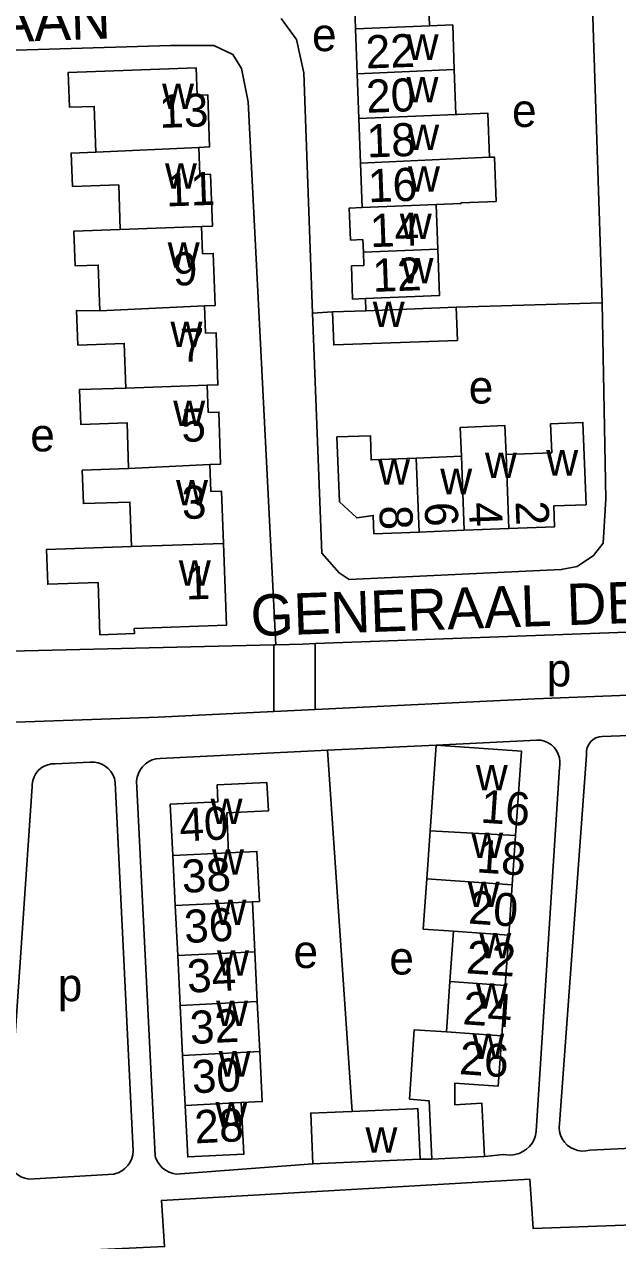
# Model space of a CAD drawing. Extents: x 159294 to 161936, y 384538 to 386517.
# Drawn here: x 161739.3 to 161811.1, y 386264.2 to 386411.4 of the extents above; entities that cross this region are included whole.
import ezdxf

# ---------------------------------------------------------------- set-up
doc = ezdxf.new("R2010")
doc.units = 0
for name, color, linetype in [('BLT_Basislijn', 7, 'Continuous'), ('BLT_Bebouwing', 7, 'Continuous'), ('BLT_Centroide', 7, 'Continuous'), ('BLT_Huisnummer', 7, 'Continuous'), ('BLT_Huisnummer_ tussenligend', 7, 'Continuous'), ('BLT_Onderverdeling_panden', 7, 'Continuous'), ('BLT_Straatnaam', 7, 'Continuous')]:
    doc.layers.add(name, color=color, linetype=linetype)

msp = doc.modelspace()

# ---------------------------------------------------------------- linework, layer by layer
at = {"layer": 'BLT_Basislijn'}
for p, q in [((161807.9, 386417.77), (161809.21, 386377.72)), ((161780.62, 386376.75), (161780.56, 386378.21)), ((161791.55, 386377.17), (161809.21, 386377.72)), ((161776.58, 386376.6), (161774.14, 386376.44)), ((161774.49, 386336.47), (161849.43, 386339.2)), ((161769.49, 386336.33), (161712.37, 386334.96)), ((161769.7, 386336.34), (161769.49, 386336.33)), ((161769.49, 386336.33), (161769.49, 386328.26)), ((161772.98, 386336.42), (161769.7, 386336.34)), ((161772.98, 386336.42), (161774.49, 386336.47)), ((161774.49, 386336.47), (161774.49, 386328.5)), ((161801.09, 386329.8), (161849.76, 386331.65)), ((161774.49, 386328.5), (161801.09, 386329.8)), ((161755.46, 386327.58), (161724.21, 386326.46)), ((161755.46, 386327.58), (161769.49, 386328.26)), ((161769.49, 386328.26), (161774.49, 386328.5)), ((161789.11, 386324.17), (161801.33, 386324.8)), ((161809.24, 386325.24), (161813.59, 386325.39)), ((161755.71, 386322.58), (161775.99, 386323.57)), ((161775.99, 386323.57), (161789.11, 386324.17)), ((161775.99, 386323.57), (161778.95, 386279.87)), ((161743.02, 386321.92), (161747.26, 386322.14)), ((161807.32, 386322.97), (161804.04, 386278.35)), ((161804.04, 386321.48), (161801.25, 386277.46)), ((161737.24, 386275.47), (161740.23, 386319.19)), ((161750.28, 386319.68), (161752.44, 386275.11)), ((161752.87, 386319.88), (161755.1, 386274.48)), ((161797.27, 386274.67), (161794.99, 386274.43)), ((161815.98, 386275.57), (161807.72, 386275.17)), ((161774.21, 386273.52), (161757.65, 386272.28)), ((161788.61, 386274.09), (161787.18, 386274.07)), ((161750.09, 386272.28), (161739.81, 386271.69))]:
    msp.add_line(p, q, dxfattribs=at)
for points in [[(161770.35, 386412.1), (161772.24, 386409.55), (161773.11, 386405.52), (161774.14, 386376.44)], [(161710.21, 386407.44), (161756.95, 386408.83), (161762.21, 386408.83), (161764.53, 386407.73), (161765.55, 386406.04), (161766.37, 386402.02), (161769.7, 386336.34)], [(161774.14, 386376.44), (161775.3, 386347.43), (161777.37, 386345.04), (161778.61, 386344.23), (161804.27, 386345.42), (161806.18, 386345.79), (161808.16, 386347.12), (161809.34, 386348.62), (161809.68, 386353.98), (161809.21, 386377.72)], [(161801.33, 386324.8), (161801.8, 386324.77), (161802.25, 386324.66), (161802.68, 386324.47), (161803.07, 386324.22), (161803.41, 386323.9), (161803.69, 386323.52), (161803.9, 386323.11), (161804.04, 386322.66), (161804.1, 386322.2), (161804.08, 386321.73), (161804.04, 386321.48)], [(161809.24, 386325.24), (161808.85, 386325.18), (161808.47, 386325.05), (161808.12, 386324.85), (161807.83, 386324.58), (161807.59, 386324.26), (161807.42, 386323.9), (161807.32, 386323.51), (161807.31, 386323.11), (161807.32, 386322.97)], [(161743.02, 386321.92), (161742.56, 386321.91), (161742.11, 386321.82), (161741.68, 386321.65), (161741.29, 386321.41), (161740.95, 386321.1), (161740.67, 386320.74), (161740.45, 386320.34), (161740.3, 386319.91), (161740.23, 386319.45), (161740.23, 386319.19)], [(161747.26, 386322.14), (161747.74, 386322.13), (161748.21, 386322.04), (161748.66, 386321.88), (161749.07, 386321.64), (161749.44, 386321.34), (161749.76, 386320.98), (161750.01, 386320.57), (161750.18, 386320.13), (161750.28, 386319.68)], [(161755.71, 386322.58), (161755.23, 386322.53), (161754.76, 386322.4), (161754.33, 386322.19), (161753.93, 386321.92), (161753.58, 386321.58), (161753.3, 386321.19), (161753.08, 386320.76), (161752.93, 386320.3), (161752.87, 386319.88)], [(161801.25, 386277.46), (161801.15, 386276.96), (161800.98, 386276.48), (161800.73, 386276.04), (161800.42, 386275.63), (161800.05, 386275.29), (161799.62, 386275), (161799.16, 386274.79), (161798.67, 386274.65), (161798.17, 386274.58), (161797.66, 386274.6), (161797.27, 386274.67)], [(161807.72, 386275.17), (161807.24, 386275.08), (161806.76, 386275.07), (161806.28, 386275.14), (161805.82, 386275.28), (161805.39, 386275.5), (161805, 386275.79), (161804.67, 386276.14), (161804.4, 386276.54), (161804.19, 386276.98), (161804.06, 386277.44), (161804.01, 386277.92), (161804.04, 386278.35)], [(161739.81, 386271.69), (161739.33, 386271.79), (161738.87, 386271.97), (161738.44, 386272.23), (161738.06, 386272.54), (161737.74, 386272.92), (161737.48, 386273.34), (161737.29, 386273.79), (161737.18, 386274.27), (161737.15, 386274.77), (161737.2, 386275.26), (161737.24, 386275.47)], [(161752.44, 386275.11), (161752.39, 386274.63), (161752.27, 386274.16), (161752.07, 386273.72), (161751.79, 386273.32), (161751.46, 386272.97), (161751.08, 386272.68), (161750.65, 386272.45), (161750.18, 386272.3), (161750.09, 386272.28)], [(161755.1, 386274.48), (161755.15, 386274.29), (161755.36, 386273.84), (161755.64, 386273.43), (161755.98, 386273.06), (161756.37, 386272.76), (161756.81, 386272.52), (161757.28, 386272.35), (161757.65, 386272.28)], [(161846.76, 386273.88), (161822.75, 386272.48), (161822.95, 386266.5), (161800.85, 386265.71), (161800.45, 386271.68), (161755.86, 386269.09), (161756.26, 386263.52), (161734.76, 386262.52), (161733.96, 386268.1)]]:
    msp.add_lwpolyline(points, dxfattribs=at)
at = {"layer": 'BLT_Bebouwing'}
for p, q in [((161779.18, 386416.22), (161779.37, 386410.84)), ((161788.34, 386411.21), (161788.14, 386416.61)), ((161779.37, 386410.84), (161779.57, 386405.41)), ((161779.57, 386405.41), (161779.77, 386399.99)), ((161779.77, 386399.99), (161779.96, 386394.6)), ((161779.96, 386394.6), (161780.16, 386389.24)), ((161789.32, 386384.2), (161789.12, 386389.6)), ((161780.62, 386376.75), (161776.58, 386376.6)), ((161791.55, 386377.17), (161780.62, 386376.75)), ((161791.7, 386373.15), (161791.55, 386377.17)), ((161792.18, 386359.13), (161786.71, 386358.92)), ((161787.07, 386349.97), (161792.53, 386350.18)), ((161792.53, 386350.18), (161797.93, 386350.4)), ((161798.74, 386313.26), (161799.45, 386323.46)), ((161788, 386308.01), (161788.4, 386313.8)), ((161798.33, 386307.29), (161798.74, 386313.26)), ((161757.25, 386310.82), (161757.55, 386304.78)), ((161797.91, 386301.2), (161798.33, 386307.29)), ((161757.55, 386304.78), (161757.85, 386298.73)), ((161767.18, 386299.19), (161766.89, 386305.24)), ((161790.79, 386295.58), (161791.21, 386301.66)), ((161797.49, 386295.11), (161797.91, 386301.2)), ((161757.85, 386298.73), (161758.15, 386292.68)), ((161767.48, 386293.15), (161767.18, 386299.19)), ((161790.37, 386289.49), (161790.79, 386295.58)), ((161797.07, 386289.02), (161797.49, 386295.11)), ((161758.15, 386292.68), (161758.44, 386286.64)), ((161767.78, 386287.1), (161767.48, 386293.15)), ((161796.65, 386282.93), (161797.07, 386289.02)), ((161758.44, 386286.64), (161758.74, 386280.59)), ((161777.87, 386279.83), (161778.95, 386279.87)), ((161778.95, 386279.87), (161786.38, 386280.19)), ((161787.18, 386274.07), (161774.21, 386273.52)), ((161788.61, 386274.09), (161794.99, 386274.43))]:
    msp.add_line(p, q, dxfattribs=at)
for points in [[(161791.32, 386405.93), (161791.13, 386411.32), (161788.34, 386411.21)], [(161760.4, 386396.51), (161761.7, 386396.56), (161761.48, 386402.87), (161760.18, 386402.82), (161760.06, 386406.12), (161744.6, 386405.58), (161744.75, 386401.37), (161747.74, 386401.47), (161747.94, 386395.93)], [(161791.52, 386400.5), (161791.32, 386405.93)], [(161795.6, 386395.31), (161795.38, 386400.67), (161791.73, 386400.51), (161791.52, 386400.5)], [(161747.94, 386395.93), (161744.94, 386395.82), (161745.09, 386391.78), (161750.7, 386391.97), (161750.89, 386386.57)], [(161760.74, 386386.92), (161762.04, 386386.97), (161761.82, 386393.27), (161760.52, 386393.23), (161760.4, 386396.51)], [(161789.12, 386389.6), (161792.15, 386389.73), (161792.14, 386389.82), (161796.38, 386389.97), (161796.18, 386395.33), (161795.6, 386395.31)], [(161780.16, 386389.24), (161778.6, 386389.17), (161778.76, 386385.29), (161780.25, 386385.35), (161780.35, 386383.85)], [(161750.89, 386386.57), (161745.27, 386386.38), (161745.42, 386382.18), (161748.23, 386382.28), (161748.42, 386376.74)], [(161761.07, 386377.33), (161762.37, 386377.37), (161762.15, 386383.69), (161760.86, 386383.64), (161760.74, 386386.92)], [(161780.35, 386383.85), (161780.37, 386382.21), (161778.86, 386382.16), (161779.01, 386378.15)], [(161780.56, 386378.21), (161789.52, 386378.58), (161789.32, 386384.2)], [(161779.01, 386378.15), (161780.56, 386378.21)], [(161748.42, 386376.74), (161745.61, 386376.79), (161745.76, 386372.59), (161751.38, 386372.79), (161751.56, 386367.39)], [(161761.42, 386367.74), (161762.71, 386367.78), (161762.49, 386374.09), (161761.19, 386374.04), (161761.07, 386377.33)], [(161776.58, 386376.6), (161776.73, 386372.62), (161791.7, 386373.15)], [(161751.56, 386367.39), (161745.95, 386367.2), (161746.1, 386363), (161751.71, 386363.19), (161751.9, 386357.65)], [(161761.75, 386358.14), (161763.04, 386358.19), (161762.82, 386364.49), (161761.53, 386364.44), (161761.42, 386367.74)], [(161797.6, 386359.34), (161797.46, 386362.86), (161792.05, 386362.63), (161792.18, 386359.13)], [(161797.93, 386350.4), (161803.47, 386350.61), (161803.37, 386353.13), (161807.28, 386353.28), (161806.89, 386363.23), (161802.98, 386363.07), (161803.12, 386359.56), (161797.6, 386359.34)], [(161786.71, 386358.92), (161781.25, 386358.7), (161781.17, 386361.63), (161777.12, 386361.47), (161777.42, 386353.61), (161779.51, 386351.68), (161781.51, 386351.98), (161781.6, 386349.76), (161787.07, 386349.97)], [(161751.9, 386357.65), (161746.29, 386357.45), (161746.43, 386353.41), (161752.05, 386353.6), (161752.24, 386348.21)], [(161763.38, 386348.6), (161763.15, 386354.9), (161761.86, 386354.86), (161761.75, 386358.14)], [(161752.24, 386348.21), (161741.95, 386347.85), (161742.1, 386343.65), (161748.21, 386343.86), (161748.43, 386337.55), (161752.6, 386337.69), (161752.58, 386338.31), (161763.73, 386338.7), (161763.38, 386348.6)], [(161789.11, 386324.17), (161788.4, 386313.8)], [(161799.45, 386323.46), (161789.11, 386324.17)], [(161764, 386311.16), (161763.77, 386315.99), (161768.83, 386316.23), (161768.65, 386319.65), (161762.6, 386319.37), (161762.71, 386317.33), (161756.94, 386317.05), (161757.25, 386310.82)], [(161766.89, 386305.24), (161767.74, 386305.28), (161767.43, 386311.33), (161764, 386311.16)], [(161791.21, 386301.66), (161787.57, 386301.92), (161788, 386308.01)], [(161790.37, 386289.49), (161786.47, 386289.74), (161785.92, 386281.34), (161788.27, 386281.16), (161788.61, 386274.09)], [(161765.54, 386280.93), (161768.08, 386281.05), (161767.78, 386287.1)], [(161791.38, 386280.67), (161791.4, 386283.3), (161796.65, 386282.93)], [(161758.74, 386280.59), (161759.05, 386274.37), (161765.85, 386274.7), (161765.54, 386280.93)], [(161794.99, 386274.43), (161794.66, 386280.85), (161791.38, 386280.67)], [(161774.21, 386273.52), (161773.95, 386279.66), (161777.87, 386279.83)], [(161786.38, 386280.19), (161786.92, 386280.21), (161787.18, 386274.07)]]:
    msp.add_lwpolyline(points, dxfattribs=at)
at = {"layer": 'BLT_Onderverdeling_panden'}
for p, q in [((161779.37, 386410.84), (161788.34, 386411.21)), ((161779.57, 386405.41), (161791.32, 386405.93)), ((161779.77, 386399.99), (161791.52, 386400.5)), ((161747.94, 386395.93), (161760.4, 386396.51)), ((161779.96, 386394.6), (161795.6, 386395.31)), ((161780.16, 386389.24), (161789.12, 386389.6)), ((161750.89, 386386.57), (161760.74, 386386.92)), ((161780.35, 386383.85), (161789.32, 386384.2)), ((161748.42, 386376.74), (161761.07, 386377.33)), ((161751.56, 386367.39), (161761.42, 386367.74)), ((161787.07, 386349.97), (161786.71, 386358.92)), ((161792.53, 386350.18), (161792.18, 386359.13)), ((161797.93, 386350.4), (161797.6, 386359.34)), ((161751.9, 386357.65), (161761.75, 386358.14)), ((161752.24, 386348.21), (161763.38, 386348.6)), ((161798.74, 386313.26), (161788.4, 386313.8)), ((161757.25, 386310.82), (161764, 386311.16)), ((161798.33, 386307.29), (161788, 386308.01)), ((161757.55, 386304.78), (161766.89, 386305.24)), ((161797.91, 386301.2), (161791.21, 386301.66)), ((161767.18, 386299.19), (161757.85, 386298.73)), ((161797.49, 386295.11), (161790.79, 386295.58)), ((161758.15, 386292.68), (161767.48, 386293.15)), ((161797.07, 386289.02), (161790.37, 386289.49)), ((161767.78, 386287.1), (161758.44, 386286.64)), ((161758.74, 386280.59), (161765.54, 386280.93))]:
    msp.add_line(p, q, dxfattribs=at)

# ---------------------------------------------------------------- texts
at = {"layer": 'BLT_Centroide'}
for s, p in [('e', (161774.1, 386408.16)), ('w', (161785.55, 386407.1)), ('w', (161755.95, 386401.16)), ('w', (161785.54, 386401.96)), ('e', (161798.31, 386398.99)), ('w', (161785.63, 386396.2)), ('w', (161756.3, 386391.53)), ('w', (161785.72, 386391.16)), ('w', (161784.73, 386385.41)), ('w', (161756.63, 386381.94)), ('w', (161784.94, 386380.06)), ('w', (161781.45, 386374.78)), ('w', (161756.97, 386372.34)), ('e', (161793.07, 386365.52)), ('w', (161757.3, 386362.78)), ('e', (161739.99, 386359.73)), ('w', (161802.45, 386356.81)), ('w', (161782.09, 386355.69)), ('w', (161795.03, 386356.52)), ('w', (161789.62, 386354.55)), ('w', (161757.64, 386353.19)), ('w', (161757.98, 386343.47)), ('p', (161802.51, 386331.29)), ('w', (161793.93, 386318.72)), ('w', (161761.82, 386314.63)), ('w', (161793.37, 386310.53)), ('w', (161761.99, 386308.5)), ('w', (161792.95, 386304.59)), ('w', (161762.29, 386302.41)), ('w', (161794.35, 386298.38)), ('e', (161771.86, 386297.22)), ('e', (161783.46, 386296.43)), ('w', (161762.6, 386296.28)), ('p', (161743.32, 386293.2)), ('w', (161793.93, 386292.31)), ('w', (161762.49, 386290.19)), ('w', (161793.51, 386286.22)), ('w', (161762.8, 386284.09)), ('w', (161762.41, 386277.94)), ('w', (161780.57, 386274.88))]:
    msp.add_text(s, height=4, dxfattribs=at).set_placement(p)
at = {"layer": 'BLT_Huisnummer'}
for s, rotation, p in [('20', 2.0762, (161780.72, 386400.69)), ('13', 2.0086, (161755.67, 386398.86)), ('16', 2.0762, (161780.94, 386389.86)), ('9', 1.9941, (161757.31, 386379.77)), ('12', 2.0762, (161781.48, 386379.02)), ('5', 1.9941, (161758.33, 386360.86)), ('8', 272.2333, (161782.23, 386353.13)), ('2', 272.2469, (161798.73, 386353.68)), ('1', 1.9941, (161758.84, 386341.79)), ('16', 356.0492, (161794.42, 386314.82)), ('40', 2.8313, (161758.13, 386312.51)), ('20', 356.0572, (161792.96, 386302.61)), ('36', 2.8313, (161758.71, 386300.23)), ('32', 2.8313, (161759.41, 386288.01)), ('26', 356.0554, (161791.84, 386284.39)), ('28', 2.8313, (161759.96, 386275.99))]:
    msp.add_text(s, height=4, rotation=rotation, dxfattribs=at).set_placement(p)
at = {"layer": 'BLT_Huisnummer_ tussenligend'}
for s, rotation, p in [('22', 2.0762, (161780.67, 386406.05)), ('18', 2.0762, (161780.78, 386395.28)), ('11', 1.9941, (161756.48, 386389.36)), ('14', 2.0762, (161781.18, 386384.43)), ('7', 1.9941, (161758.2, 386370.55)), ('3', 1.9941, (161758.4, 386351.53)), ('6', 272.2469, (161787.72, 386353.53)), ('4', 272.2469, (161793.08, 386353.53)), ('18', 356.0492, (161793.93, 386308.8)), ('38', 2.8313, (161758.42, 386306.3)), ('22', 356.0572, (161792.68, 386296.59)), ('34', 2.8313, (161759.06, 386294.22)), ('24', 356.0572, (161792.27, 386290.42)), ('30', 2.8313, (161759.65, 386282.05))]:
    msp.add_text(s, height=4, rotation=rotation, dxfattribs=at).set_placement(p)
at = {"layer": 'BLT_Straatnaam'}
for p in [(161656.58, 386406.43), (161766.75, 386337.36)]:
    msp.add_text('GENERAAL DE GAULLELAAN', height=5, rotation=2.0007, dxfattribs=at).set_placement(p)

doc.saveas('drawing.dxf')
